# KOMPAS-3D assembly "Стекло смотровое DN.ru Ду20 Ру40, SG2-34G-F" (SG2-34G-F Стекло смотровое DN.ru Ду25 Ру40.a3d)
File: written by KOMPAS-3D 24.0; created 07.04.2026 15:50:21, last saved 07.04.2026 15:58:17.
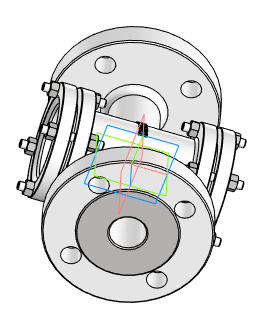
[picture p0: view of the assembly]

Document properties: Автор: Main; Полное имя файла: D:\DN.ru Аутсерс\Стекло смотровое DN.ru\Исходники\Стекло смотровое DN.ru SG2-34G-F тип В ГОСТ 21836-2021 Ду25 Ру40, углеродистая сталь, фланцевое\SG2-34G-F Стекло смотровое DN.ru Ду25 Ру40.a3d

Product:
- Component [detail]: Деталь  | qty 1  | pos. 1  | Масса: 4.198388; Автор: Main; additional columns: Типовые; source file: ДетальДеталь.m3d
- Component [detail]: Стекло  | qty 2  | pos. 2  | Масса: 0.08342; Автор: Main; source file: СтеклоСтекло.m3d
- Component [detail]: ANSI B18.2.4.2M - M6x1 - 10  | designation ANSI B18.2.4.2M - M6x1  | qty 16  | pos. 3  | Масса: 0.003008; Комментарий: Типы метрических   шестигранных гаек   2; Автор: Main; additional columns: Сталь, мягкая; source file: ANSI B18.2.4.2M - M6x1ANSI B18.2.4.2M - M6x1 - 10.m3d
- Part/product: Стекло смотровое DN.ru Ду20 Ру40  | designation SG2-34G-F
    Масса: 5.5
    Раздел спецификации: Прочие изделия
    Примечание: D500-00081

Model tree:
1. Массив по концентрической сетке:1  (labels: Грань.Твердое тело1; Ребро.Solid1; Грань.Solid1; Ребро.Твердое тело1)  (4 pattern instances)
     Шаг 2 = 360

Expressions: SG2-34G-F
Referenced files in D:\DN.ru Аутсерс\Стекло смотровое DN.ru\Исходники\Стекло смотровое DN.ru SG2-34G-F тип В ГОСТ 21836-2021 Ду25 Ру40, углеродистая сталь, фланцевое\: ДетальДеталь.m3d, СтеклоСтекло.m3d, ANSI B18.2.4.2M - M6x1ANSI B18.2.4.2M - M6x1 - 10.m3d
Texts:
  Стекло Стекло (1)
  Стекло Стекло (2)
  ANSI B18.2.4.2M - M6x1 ANSI B18.2.4.2M - M6x1 - 10 (1)
  ANSI B18.2.4.2M - M6x1 ANSI B18.2.4.2M - M6x1 - 10 (2)
  ANSI B18.2.4.2M - M6x1 ANSI B18.2.4.2M - M6x1 - 10 (3)
  ANSI B18.2.4.2M - M6x1 ANSI B18.2.4.2M - M6x1 - 10 (4)
  ANSI B18.2.4.2M - M6x1 ANSI B18.2.4.2M - M6x1 - 10 (5)
  ANSI B18.2.4.2M - M6x1 ANSI B18.2.4.2M - M6x1 - 10 (6)
  ANSI B18.2.4.2M - M6x1 ANSI B18.2.4.2M - M6x1 - 10 (7)
  ANSI B18.2.4.2M - M6x1 ANSI B18.2.4.2M - M6x1 - 10 (8)
  ANSI B18.2.4.2M - M6x1 ANSI B18.2.4.2M - M6x1 - 10 (9)
  ANSI B18.2.4.2M - M6x1 ANSI B18.2.4.2M - M6x1 - 10 (10)
  ANSI B18.2.4.2M - M6x1 ANSI B18.2.4.2M - M6x1 - 10 (11)
  ANSI B18.2.4.2M - M6x1 ANSI B18.2.4.2M - M6x1 - 10 (12)
  ANSI B18.2.4.2M - M6x1 ANSI B18.2.4.2M - M6x1 - 10 (13)
  ANSI B18.2.4.2M - M6x1 ANSI B18.2.4.2M - M6x1 - 10 (14)
  ANSI B18.2.4.2M - M6x1 ANSI B18.2.4.2M - M6x1 - 10 (15)
  ANSI B18.2.4.2M - M6x1 ANSI B18.2.4.2M - M6x1 - 10 (16)
  Ось Z.Начало координат
  Ось X.Начало координат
